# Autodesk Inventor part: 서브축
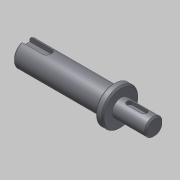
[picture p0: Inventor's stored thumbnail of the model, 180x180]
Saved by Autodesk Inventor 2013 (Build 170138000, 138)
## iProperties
Created: 2018-09
Part Number: 서브축
Document SubType Name: Modeling
Density: 7.86 g/cm^3
Material: 강철, 연강
Mass: 142.802 g
Surface Area: 54.794 cm^2
Volume: 18.1682 cm^3
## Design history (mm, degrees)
sketch "스케치1"
  geometry: L1 (-18.818, -7)-(-18.818, 7) reference; L2 (-41.331, -13.5)-(-41.331, 13.5) reference; L3 (-46.5, 12.249)-(-46.5, -12.249) reference; L4 (-18.331, 0)-(-106.5, 0); L5 (-18.331, 0)-(-18.331, -6); L6 (-18.331, -6)-(-41.331, -6); L7 (-41.331, -12.5)-(-46.5, -12.5); L8 (-46.5, -8.5)-(-106.5, -8.5); L9 (-106.5, -8.5)-(-106.5, 0); L10 (-46.5, -8.5)-(-46.5, -12.5); L11 (-41.331, -6)-(-41.331, -12.5); 2 further points
  constraints: 17 end point, 5 point on line, 3 parallel, 3 perpendicular, 2 collinear, 1 midpoint
  dimensions: "d0" = 23 distance between parallel lines of L2 L5; "d1" = 12 diameter of L6 L4; "d2" = 25 diameter of L7 L4; "d3" = 17 diameter of L8 L4; "d4" = 60 distance of L8.start L8.end
revolve "회전1" sketch "스케치1" stored, may be unused: angle "d5" = 90 deg
chamfer "모따기1" distance "d6" = 1; stored, may be unused: second distance "d7" = 2, angle "d8" = 45 deg
node "작업 평면1"
sketch "스케치2"
  geometry: L1 (11.5, 5)-(11.5, -5) reference; L2 (-5.5, -2)-(4.5, -2); L3 (4.5, 2)-(-5.5, 2); A1 r 2 centre (4.5, 0) between (4.5, -2) and (4.5, 2); A2 r 2 centre (-5.5, 0) between (-5.5, 2) and (-5.5, -2); 2 further points
  constraints: 4 end point, 4 point on circle, 4 tangent, 2 centre point, 1 horizontal alignment, 1 midpoint, 1 parallel, 1 perpendicular
  dimensions: "d9" = 4 distance between parallel lines of L2 L3; "d10" = 14 dimension on A1 A2; "d11" = 5 distance edge to line of A1 L1
extrude "돌출1" cut sketch "스케치2" distance "d12" = 2.5; taper "d13" = 0 deg
node "작업 평면2"
sketch "스케치3"
  geometry: L1 (-30, -7.5)-(-30, 7.5) reference; L2 (-30, 3)-(-15, 3); L3 (-15, -3)-(-30, -3); A1 r 3 centre (-15, 0) between (-15, -3) and (-15, 3); 2 further points
  constraints: 4 end point, 2 perpendicular, 2 point on circle, 2 point on line, 2 tangent, 1 centre point, 1 horizontal alignment, 1 midpoint
  dimensions: "d14" = 6 distance between parallel lines of L3 L2; "d15" = 18 dimension on A1 L1
extrude "돌출2" cut sketch "스케치3" distance "d16" = 3.5; taper "d17" = 0 deg
node "솔리드1"
node "참조1"
node "참조2"
node "참조3"
